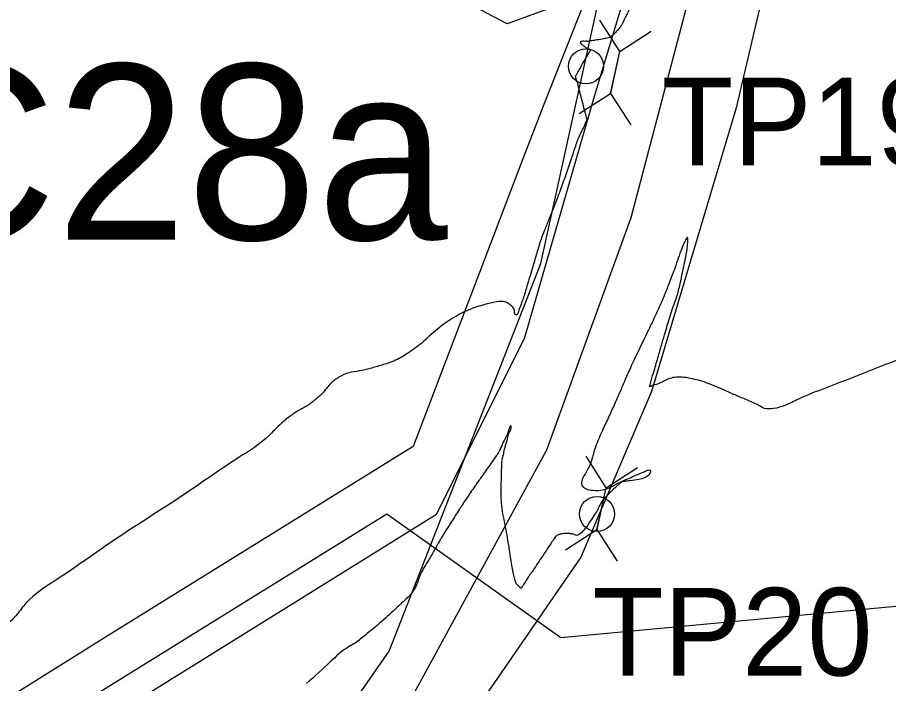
# Model space of a CAD drawing. Extents: x -478645 to -472650, y -1118147 to -1113892.
# Drawn here: x -475228.9 to -475129.6, y -1114930.1 to -1114854.1 of the extents above; entities that cross this region are included whole.
import ezdxf

# ---------------------------------------------------------------- set-up
doc = ezdxf.new("R2010")
doc.units = 0
for name, color, linetype in [('cesty', 7, 'Continuous'), ('el vedeni_NN', 7, 'Continuous'), ('ObPÚ', 7, 'Continuous'), ('silnice', 7, 'Continuous'), ('telekomunikační kabel_O2', 7, 'Continuous'), ('TP_stavajicí_mosty', 7, 'Continuous'), ('VAK_vodovod', 7, 'Continuous'), ('Vrstevnice_hlavni', 7, 'Continuous'), ('Vrstevnice_vedlejsi', 7, 'Continuous')]:
    doc.layers.add(name, color=color, linetype=linetype)

msp = doc.modelspace()

# ---------------------------------------------------------------- linework, layer by layer
at = {"layer": 'cesty'}
for centre in [(-475164.077, -1114859.704), (-475162.822, -1114910.77)]:
    msp.add_circle(centre, 2, dxfattribs=at)
at = {"layer": 'el vedeni_NN'}
msp.add_lwpolyline([(-475215.612, -1114968.264), (-475186.525, -1114926.411), (-475169.243, -1114882.212), (-475159.519, -1114837.935), (-475151.589, -1114788.244), (-475145.673, -1114747.055), (-475138.473, -1114703.021), (-475131.546, -1114660.269), (-475122.659, -1114616.897), (-475110.709, -1114574.217), (-475099.759, -1114536.24), (-475098.72, -1114533.42)], dxfattribs=at)
at = {"layer": 'ObPÚ'}
for points in [[(-475141.35, -1114840.62), (-475146.97, -1114864.46), (-475156.61, -1114896.79), (-475164.69, -1114915.68), (-475219.79, -1114995.68), (-475246.38, -1115030.84), (-475297.89, -1115099.08)], [(-475295.51, -1114985.51), (-475271.41, -1114967.52), (-475248.62, -1114952.7), (-475181.13, -1114910.79), (-475171.09, -1114890.74), (-475163.18, -1114863.39), (-475159.09, -1114849.73), (-475173.07, -1114854.88), (-475180.98, -1114850.67)]]:
    msp.add_lwpolyline(points, dxfattribs=at)
at = {"layer": 'silnice'}
msp.add_lwpolyline([(-476261.922, -1115907.288), (-476203.622, -1115869.922), (-476022.083, -1115758.582), (-475811.314, -1115629.283), (-475771.826, -1115610.299), (-475706.185, -1115581.566), (-475629.775, -1115551.807), (-475577.467, -1115527.178), (-475544.647, -1115503.063), (-475523.184, -1115471.236), (-475482.102, -1115402.498), (-475367.21, -1115204.445), (-475326.334, -1115129.255), (-475275.418, -1115058.05), (-475221.516, -1114984.557), (-475183.897, -1114931.624), (-475168.551, -1114903.46), (-475158.95, -1114876.948), (-475149.714, -1114842.011)], dxfattribs=at)
at = {"layer": 'telekomunikační kabel_O2'}
for points in [[(-475160.66, -1114839.2), (-475163.01, -1114849.14), (-475168.98, -1114864.26), (-475171.29, -1114870.25)], [(-475171.29, -1114870.25), (-475183.8, -1114903.08), (-475218.7, -1114924.7), (-475240.19, -1114938.11), (-475252.96, -1114946.28), (-475275.76, -1114962.76)]]:
    msp.add_lwpolyline(points, dxfattribs=at)
at = {"layer": 'TP_stavajicí_mosty'}
for p, q in [((-475160.215, -1114858.039), (-475162.506, -1114854.441)), ((-475160.221, -1114858.038), (-475156.645, -1114855.714)), ((-475161.272, -1114862.809), (-475160.215, -1114858.039)), ((-475161.238, -1114862.816), (-475160.221, -1114858.038)), ((-475164.867, -1114865.104), (-475161.272, -1114862.809)), ((-475158.918, -1114866.395), (-475161.238, -1114862.816)), ((-475161.777, -1114907.77), (-475164.067, -1114904.171)), ((-475161.783, -1114907.768), (-475158.207, -1114905.444)), ((-475162.833, -1114912.539), (-475161.777, -1114907.77)), ((-475162.8, -1114912.546), (-475161.783, -1114907.768)), ((-475166.429, -1114914.834), (-475162.833, -1114912.539)), ((-475160.48, -1114916.126), (-475162.8, -1114912.546))]:
    msp.add_line(p, q, dxfattribs=at)
at = {"layer": 'VAK_vodovod'}
msp.add_lwpolyline([(-474353.107, -1114953.583), (-474361.61, -1114958.706), (-474595.715, -1114908.889), (-474915.032, -1114913.356), (-475071.406, -1114915.967), (-475166.959, -1114924.877), (-475186.791, -1114910.776), (-475249.967, -1114949.925), (-475380.04, -1115027.919), (-475382.053, -1115026.738)], dxfattribs=at)
at = {"layer": 'Vrstevnice_hlavni'}
for points in [[(-475096.033, -1114887.087), (-475105.505, -1114888.868), (-475109.747, -1114889.49), (-475113.494, -1114889.843), (-475116.747, -1114889.927), (-475120.947, -1114890.753), (-475126.094, -1114892.319), (-475132.189, -1114894.627), (-475136.771, -1114896.407), (-475139.841, -1114897.66), (-475141.399, -1114898.385), (-475142.693, -1114898.739), (-475143.722, -1114898.72), (-475144.486, -1114898.33), (-475145.848, -1114897.713), (-475147.807, -1114896.867), (-475150.363, -1114895.795), (-475152.486, -1114895.245), (-475154.178, -1114895.217), (-475155.438, -1114895.712), (-475156.281, -1114896.046), (-475156.707, -1114896.218), (-475156.716, -1114896.23), (-475156.731, -1114896.235), (-475156.752, -1114896.235), (-475156.779, -1114896.229), (-475156.802, -1114896.228), (-475156.821, -1114896.232), (-475156.836, -1114896.24), (-475156.843, -1114896.236), (-475156.841, -1114896.218), (-475156.83, -1114896.188), (-475156.821, -1114896.162), (-475156.814, -1114896.14), (-475156.808, -1114896.123), (-475156.641, -1114895.55), (-475156.312, -1114894.422), (-475155.821, -1114892.739), (-475155.394, -1114891.267), (-475155.03, -1114890.006), (-475154.73, -1114888.956), (-475154.413, -1114887.939), (-475154.081, -1114886.954), (-475153.733, -1114886.002), (-475153.353, -1114884.538), (-475152.94, -1114882.561), (-475152.495, -1114880.072), (-475152.496, -1114879.218), (-475152.944, -1114879.997), (-475153.838, -1114882.411), (-475154.563, -1114884.329), (-475155.122, -1114885.75), (-475155.512, -1114886.676), (-475156.126, -1114888.024), (-475156.963, -1114889.795), (-475158.025, -1114891.989), (-475158.916, -1114893.884), (-475159.637, -1114895.482), (-475160.188, -1114896.782), (-475160.797, -1114898.163), (-475161.463, -1114899.625), (-475162.187, -1114901.169), (-475162.729, -1114902.416), (-475163.09, -1114903.366), (-475163.27, -1114904.019), (-475163.407, -1114904.51), (-475163.501, -1114904.838), (-475163.551, -1114905.005), (-475163.739, -1114905.395), (-475164.064, -1114906.009), (-475164.527, -1114906.847), (-475164.547, -1114907.467), (-475164.124, -1114907.87), (-475163.259, -1114908.056), (-475162.426, -1114908.05), (-475161.624, -1114907.853), (-475160.854, -1114907.464), (-475160.339, -1114907.204), (-475160.081, -1114907.073), (-475160.079, -1114907.071), (-475160.075, -1114907.07), (-475160.07, -1114907.067), (-475160.064, -1114907.065), (-475159.814, -1114906.956), (-475159.32, -1114906.741), (-475158.581, -1114906.419), (-475157.946, -1114906.146), (-475157.415, -1114905.921), (-475156.988, -1114905.746), (-475156.764, -1114905.754), (-475156.743, -1114905.945), (-475156.924, -1114906.32), (-475157.368, -1114906.615), (-475158.073, -1114906.829), (-475159.041, -1114906.963), (-475159.692, -1114907.058), (-475160.027, -1114907.113)], [(-475160.027, -1114907.113), (-475160.045, -1114907.128), (-475160.289, -1114907.351), (-475160.759, -1114907.781), (-475161.455, -1114908.418), (-475162.013, -1114909.027), (-475162.432, -1114909.609), (-475162.713, -1114910.163), (-475163.101, -1114910.823), (-475163.596, -1114911.589), (-475164.198, -1114912.459), (-475164.721, -1114912.997), (-475165.166, -1114913.202), (-475165.534, -1114913.074), (-475165.94, -1114913.002), (-475166.385, -1114912.987), (-475166.87, -1114913.028), (-475167.248, -1114913.132), (-475167.52, -1114913.3), (-475167.686, -1114913.532), (-475168.06, -1114914.084), (-475168.642, -1114914.956), (-475169.432, -1114916.15), (-475169.993, -1114916.989), (-475170.325, -1114917.475), (-475170.429, -1114917.607), (-475170.609, -1114917.872), (-475170.865, -1114918.27), (-475171.199, -1114918.8), (-475171.429, -1114919.13), (-475171.557, -1114919.258), (-475171.583, -1114919.185), (-475171.659, -1114919.085), (-475171.787, -1114918.958), (-475171.966, -1114918.804), (-475172.134, -1114918.462), (-475172.289, -1114917.932), (-475172.432, -1114917.216), (-475172.582, -1114916.374), (-475172.738, -1114915.406), (-475172.901, -1114914.312), (-475173.091, -1114913.168), (-475173.307, -1114911.974), (-475173.55, -1114910.73), (-475173.704, -1114909.513), (-475173.77, -1114908.323), (-475173.746, -1114907.159), (-475173.721, -1114906.223), (-475173.693, -1114905.513), (-475173.664, -1114905.03), (-475173.645, -1114904.708), (-475173.636, -1114904.546), (-475173.637, -1114904.545), (-475173.572, -1114904.28), (-475173.443, -1114903.752), (-475173.248, -1114902.959), (-475173.045, -1114902.202), (-475172.834, -1114901.48), (-475172.615, -1114900.793), (-475172.641, -1114900.715), (-475172.913, -1114901.248), (-475173.43, -1114902.391), (-475173.791, -1114903.186), (-475173.998, -1114903.634), (-475174.049, -1114903.734), (-475174.404, -1114904.254), (-475175.062, -1114905.194), (-475176.024, -1114906.554), (-475176.756, -1114907.594), (-475177.259, -1114908.312), (-475177.531, -1114908.711), (-475178, -1114909.426), (-475178.666, -1114910.456), (-475179.529, -1114911.804), (-475180.173, -1114912.821), (-475180.598, -1114913.509), (-475180.805, -1114913.868), (-475181.044, -1114914.29), (-475181.314, -1114914.776), (-475181.615, -1114915.326), (-475181.919, -1114915.85), (-475182.226, -1114916.347), (-475182.536, -1114916.818), (-475182.814, -1114917.332), (-475183.061, -1114917.89), (-475183.276, -1114918.49), (-475183.506, -1114919.015), (-475183.751, -1114919.465), (-475184.01, -1114919.84), (-475184.79, -1114920.631), (-475186.091, -1114921.84), (-475187.911, -1114923.466), (-475189.399, -1114924.71), (-475190.555, -1114925.571), (-475191.377, -1114926.05), (-475193.177, -1114927.56), (-475195.955, -1114930.1)]]:
    msp.add_spline(points, degree=3, dxfattribs=at)
at = {"layer": 'Vrstevnice_vedlejsi'}
for points in [[(-475161.298, -1114788.858), (-475162.089, -1114789.137), (-475162.681, -1114789.399), (-475163.075, -1114789.644), (-475163.27, -1114789.873), (-475163.049, -1114790.323), (-475162.409, -1114790.996), (-475161.352, -1114791.891), (-475159.977, -1114792.746), (-475158.284, -1114793.56), (-475156.274, -1114794.334), (-475154.492, -1114794.908), (-475152.938, -1114795.284), (-475151.612, -1114795.459), (-475151.088, -1114798.594), (-475151.365, -1114804.688), (-475152.442, -1114813.74), (-475153.189, -1114820.23), (-475153.605, -1114824.156), (-475153.69, -1114825.52), (-475153.87, -1114827.155), (-475154.144, -1114829.063), (-475154.514, -1114831.243), (-475154.771, -1114832.716), (-475154.913, -1114833.483), (-475154.943, -1114833.543), (-475155.062, -1114834.208), (-475155.272, -1114835.476), (-475155.571, -1114837.348), (-475155.614, -1114839.164), (-475155.401, -1114840.923), (-475154.93, -1114842.626), (-475155.053, -1114844.559), (-475155.768, -1114846.721), (-475157.077, -1114849.114), (-475157.965, -1114850.752), (-475158.433, -1114851.635), (-475158.48, -1114851.764), (-475158.535, -1114851.917), (-475158.597, -1114852.094), (-475158.668, -1114852.295), (-475158.824, -1114852.632), (-475159.066, -1114853.106), (-475159.393, -1114853.716), (-475159.645, -1114854.208), (-475159.822, -1114854.582), (-475159.924, -1114854.838), (-475160.12, -1114855.148), (-475160.411, -1114855.51), (-475160.796, -1114855.925), (-475161.084, -1114856.216), (-475161.273, -1114856.384), (-475161.364, -1114856.429), (-475161.687, -1114856.503), (-475162.242, -1114856.606), (-475163.03, -1114856.739), (-475163.577, -1114856.826), (-475163.883, -1114856.867), (-475163.949, -1114856.863), (-475164.096, -1114856.862), (-475164.325, -1114856.864), (-475164.635, -1114856.87), (-475164.739, -1114856.959), (-475164.636, -1114857.132), (-475164.326, -1114857.388), (-475164.085, -1114857.573), (-475163.912, -1114857.688), (-475163.806, -1114857.731), (-475163.716, -1114857.768), (-475163.642, -1114857.798), (-475163.583, -1114857.822), (-475163.587, -1114857.897), (-475163.654, -1114858.022), (-475163.784, -1114858.198), (-475164.018, -1114858.58), (-475164.356, -1114859.167), (-475164.798, -1114859.96), (-475165.098, -1114860.496), (-475165.255, -1114860.775), (-475165.269, -1114860.797), (-475165.28, -1114860.813), (-475165.286, -1114860.823), (-475165.287, -1114860.828), (-475165.288, -1114860.833), (-475165.288, -1114860.841), (-475165.288, -1114860.85), (-475165.15, -1114861.376), (-475164.874, -1114862.419), (-475164.461, -1114863.979), (-475164.178, -1114865.053), (-475164.024, -1114865.642), (-475164, -1114865.745), (-475164.094, -1114866.041), (-475164.307, -1114866.532), (-475164.638, -1114867.216), (-475164.873, -1114867.71), (-475165.01, -1114868.013)], [(-475165.01, -1114868.013), (-475165.05, -1114868.125), (-475165.281, -1114868.806), (-475165.703, -1114870.055), (-475166.317, -1114871.871), (-475166.957, -1114873.663), (-475167.624, -1114875.428), (-475168.318, -1114877.168), (-475168.812, -1114878.412), (-475169.106, -1114879.158), (-475169.2, -1114879.408), (-475169.471, -1114880.277), (-475169.92, -1114881.765), (-475170.546, -1114883.871), (-475170.973, -1114885.3), (-475171.2, -1114886.053), (-475171.229, -1114886.13), (-475171.338, -1114886.431), (-475171.527, -1114886.958), (-475171.797, -1114887.71), (-475172.007, -1114888.06), (-475172.156, -1114888.007), (-475172.246, -1114887.551), (-475172.473, -1114887.157), (-475172.838, -1114886.826), (-475173.341, -1114886.558), (-475174.274, -1114886.578), (-475175.638, -1114886.886), (-475177.432, -1114887.482), (-475179.227, -1114888.41), (-475181.023, -1114889.671), (-475182.821, -1114891.264), (-475184.477, -1114892.48), (-475185.992, -1114893.32), (-475187.365, -1114893.784), (-475188.68, -1114894.162), (-475189.935, -1114894.455), (-475191.133, -1114894.663), (-475192.214, -1114895.133), (-475193.181, -1114895.865), (-475194.031, -1114896.859), (-475194.962, -1114897.727), (-475195.973, -1114898.469), (-475197.065, -1114899.086), (-475198.134, -1114899.846), (-475199.182, -1114900.749), (-475200.207, -1114901.796), (-475203.748, -1114904.366), (-475209.805, -1114908.459), (-475218.377, -1114914.075), (-475224.429, -1114918.234), (-475227.959, -1114920.938), (-475228.969, -1114922.186), (-475230.227, -1114923.491), (-475231.733, -1114924.853), (-475233.487, -1114926.271), (-475235.347, -1114927.66), (-475237.312, -1114929.021), (-475239.383, -1114930.353), (-475241.54, -1114932.436), (-475243.781, -1114935.27), (-475246.108, -1114938.856), (-475248.144, -1114941.939), (-475249.888, -1114944.521), (-475251.341, -1114946.601), (-475252.97, -1114948.481), (-475254.775, -1114950.161), (-475256.756, -1114951.642), (-475258.525, -1114952.91), (-475260.083, -1114953.964), (-475261.428, -1114954.805), (-475262.907, -1114956.088), (-475264.519, -1114957.812), (-475266.265, -1114959.977), (-475267.432, -1114961.438), (-475268.017, -1114962.196), (-475268.023, -1114962.249), (-475268.028, -1114962.299), (-475268.032, -1114962.347), (-475268.035, -1114962.391), (-475267.548, -1114962.323), (-475266.572, -1114962.143), (-475265.105, -1114961.85), (-475264.939, -1114962.323), (-475266.073, -1114963.561), (-475268.508, -1114965.565), (-475270.111, -1114967.349), (-475270.881, -1114968.915), (-475270.819, -1114970.261), (-475271.092, -1114971.257), (-475271.701, -1114971.903), (-475272.646, -1114972.199), (-475273.37, -1114972.395), (-475273.874, -1114972.492), (-475274.158, -1114972.489), (-475274.425, -1114972.486), (-475274.673, -1114972.482)]]:
    msp.add_spline(points, degree=3, dxfattribs=at)

# ---------------------------------------------------------------- texts
at = {"layer": 'cesty'}
msp.add_text('C28a', height=20, rotation=359.99999, dxfattribs=at).set_placement((-475243.813, -1114879.476))
at = {"layer": 'TP_stavajicí_mosty'}
for s, p in [('TP19', (-475155.447, -1114871.013)), ('TP20', (-475163.372, -1114929.188))]:
    msp.add_text(s, height=10, rotation=359.99999, dxfattribs=at).set_placement(p)

doc.saveas('drawing.dxf')
